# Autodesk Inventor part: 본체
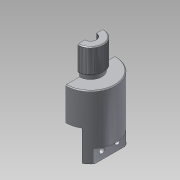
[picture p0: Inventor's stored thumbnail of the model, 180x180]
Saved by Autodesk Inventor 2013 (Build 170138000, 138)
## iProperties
Created: 2019-02
Part Number: 본체
Material: 알루미늄 6061
Document SubType Name: Modeling
Designer: Administrator
Density: 2.71 g/cm^3
Mass: 345.756 g
Surface Area: 298.528 cm^2
Volume: 127.585 cm^3
Author: Administrator
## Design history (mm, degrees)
sketch "스케치1"
  geometry: C1 r 29 at (0, 0); 1 further point
  constraints: 1 centre point, 1 coincident
  dimensions: "d0" = 58 diameter of C1
extrude "돌출1" new body sketch "스케치1" distance "d1" = 38; taper "d3" = 0 deg; dims "d2" = 36, "d4" = 0
sketch "스케치2"
  geometry: C1 r 13 at (0, 0); 1 further point
  constraints: 1 centre point, 1 coincident
  dimensions: "d5" = 26 diameter of C1
extrude "돌출2" join sketch "스케치2" distance "d6" = 5; taper "d7" = 0 deg
sketch "스케치3"
  geometry: C1 r 13 at (0, 0) reference; C2 r 15 at (0, 0)
  constraints: 1 centre point, 1 coincident
  dimensions: "d9" = 30 diameter of C2
extrude "돌출3" join sketch "스케치3" distance "d10" = 29; taper "d11" = 0 deg
hole "구멍1" diameter "d14" = 13.376; stored, may be unused: countersink angle "d18" = 90 deg, drill point angle "d20" = 118 deg; dims "d15" = 18, "d16" = 4, "d17" = 2, "d19" = 22, "d80" = 10, "d81" = 10
feature "스레드1" dims "d21" = 10, "d22" = 0
chamfer "모따기1" distance "d23" = 1; stored, may be unused: second distance "d24" = 2, angle "d25" = 45 deg
sketch "스케치5"
  geometry: L1 (-15, 0)-(15, 0); L2 (15, 0)-(15, -36); L3 (15, -36)-(-15, -36); L4 (-15, -36)-(-15, 0); L5 (-29, -36)-(29, -36) reference; L6 (-29, -20)-(-22, -20); L7 (-22, -20)-(-22, -36); L8 (-22, -36)-(-29, -36); L9 (-29, -36)-(-29, -20); L10 (29, -20)-(22, -20); L11 (22, -20)-(22, -36); L12 (22, -36)-(29, -36); L13 (29, -36)-(29, -20); L14 (-29, -36)-(-29, 38) reference; L15 (-29, -36)-(29, -36) reference; L16 (29, 38)-(-29, 38) reference; L17 (29, -36)-(29, 38) reference; 2 further points
  constraints: 24 end point, 6 parallel, 3 horizontal, 3 perpendicular, 2 collinear, 2 equal length, 2 midpoint, 2 point on line
  dimensions: "d31" = 36 distance of L3.end L1.start; "d33" = 30 distance of L2.end L3.end; "d36" = 16 distance of L12.end L10.start; "d37" = 44 distance between parallel lines of L11 L7
extrude "돌출5" cut sketch "스케치5" stored distance "d34" = 29; taper "d35" = 0 deg
sketch "스케치6"
  geometry: L1 (0, 0)-(0, 37.789) reference; 3 further points
  constraints: 1 vertical alignment
  dimensions: "d38" = 18 distance of point (9, 9.894) point (9, 27.894); "d40" = 9 distance from line of point (9, 9.894) L1; "d41" = 9 vertical distance of point (36, 18.894) point (9, 27.894)
hole "구멍2" sketch "스케치6" at (9, 27.894), (9, 9.894) diameter "d42" = 6; stored, may be unused: countersink angle "d46" = 90 deg, drill point angle "d48" = 118 deg; dims "d43" = 18, "d44" = 4, "d45" = 2, "d47" = 22
chamfer "모따기2" distance "d49" = 1; stored, may be unused: second distance "d50" = 2, angle "d51" = 45 deg
sketch "스케치7"
  geometry: C1 r 14 at (0, 0); A1 r 29 centre (0, 0) between (15, 24.819) and (-15, 24.819) reference
  constraints: 1 centre point, 1 coincident
  dimensions: "d68" = 28 diameter of C1
extrude "돌출6" cut sketch "스케치7" distance "d53" = 20; taper "d54" = 0 deg
sketch "스케치10"
  geometry: C1 r 4 at (0, 0) reference; C2 r 14 at (0, 0) reference; C3 r 16 at (0, 0)
  constraints: 1 centre point, 1 coincident
  dimensions: "d70" = 32 diameter of C3
extrude "돌출8" cut sketch "스케치10" distance "d72" = 7; taper "d73" = 0 deg
sketch "스케치12"
  geometry: C1 r 4 at (0, 0) reference
extrude "돌출9" cut sketch "스케치12" stored distance "d82" = 7; taper "d83" = 0 deg
sketch "스케치15"
  geometry: L1 (-17, 2.65)-(-14, 2.65); L2 (-14, 2.65)-(-14, 7.35); L3 (-14, 7.35)-(-17, 7.35); L4 (-17, 7.35)-(-17, 2.65); L5 (-17, 11.65)-(-14, 11.65); L6 (-14, 11.65)-(-14, 16.35); L7 (-14, 16.35)-(-17, 16.35); L8 (-17, 16.35)-(-17, 11.65); L9 (-14, 0)-(-14, 20) reference; L10 (24.819, 0)-(-24.819, 0) reference; L11 (0, 0)-(0, 11.65); L12 (14, 0)-(14, 20) reference; 2 further points
  constraints: 18 end point, 4 parallel, 3 perpendicular, 2 collinear, 2 equal length, 2 horizontal, 2 midpoint
  dimensions: "d102" = 5 distance from line of point (-17, 5) L10; "d103" = 9 distance of point (-17, 14) point (-17, 5); "d104" = 4.7 distance of L1.end L2.end; "d105" = 3 distance of L1.start L1.end
revolve "회전3" sketch "스케치15" stored, may be unused: angle "d106" = 90 deg
fillet "모깎기2" dims "d84" = 0.8
chamfer "모따기4" distance "d85" = 1; stored, may be unused: second distance "d86" = 2, angle "d87" = 45 deg
node "작업 평면1"
sketch "스케치13"
  geometry: L1 (-5, 33)-(5, 33); L2 (5, 33)-(5, -7); L3 (5, -7)-(-5, -7); L4 (-5, -7)-(-5, 33); L5 (29, 38)-(-29, 38) reference; 2 further points
  constraints: 8 end point, 2 parallel, 1 horizontal, 1 midpoint, 1 perpendicular, 1 vertical alignment
  dimensions: "d89" = 40 distance of L1.end L2.end; "d91" = 10 distance of L1.start L1.end; "d92" = 5 distance between parallel lines of L1 L5
extrude "돌출10" join sketch "스케치13" stored distance "d93" = 7; taper "d94" = 0 deg
sketch "스케치14"
  geometry: L1 (-7, 5)-(-7, -5) reference; L2 (-7, -5)-(33, -5) reference; 2 further points
  constraints: 1 other
  dimensions: "d95" = 20 distance from line of point (13, 0) L1; "d96" = 5 distance from line of point (13, 0) L2
feature "엠보싱1" sketch "스케치14" dims "d97" = 0.5, "d98" = 0
chamfer "모따기5" distance "d99" = 1; stored, may be unused: second distance "d100" = 2, angle "d101" = 45 deg
node "솔리드1"
node "투영된 루프1"
